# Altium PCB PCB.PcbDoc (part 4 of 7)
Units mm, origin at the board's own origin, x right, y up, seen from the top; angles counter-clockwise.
Board outline 243.2 x 142.8 mm, 4 copper layers (Top Layer, Layer 1, Layer 2, Bottom Layer), stack 0.603 mm thick; 451 components, 380 nets, 2276 pads, 1520 vias.
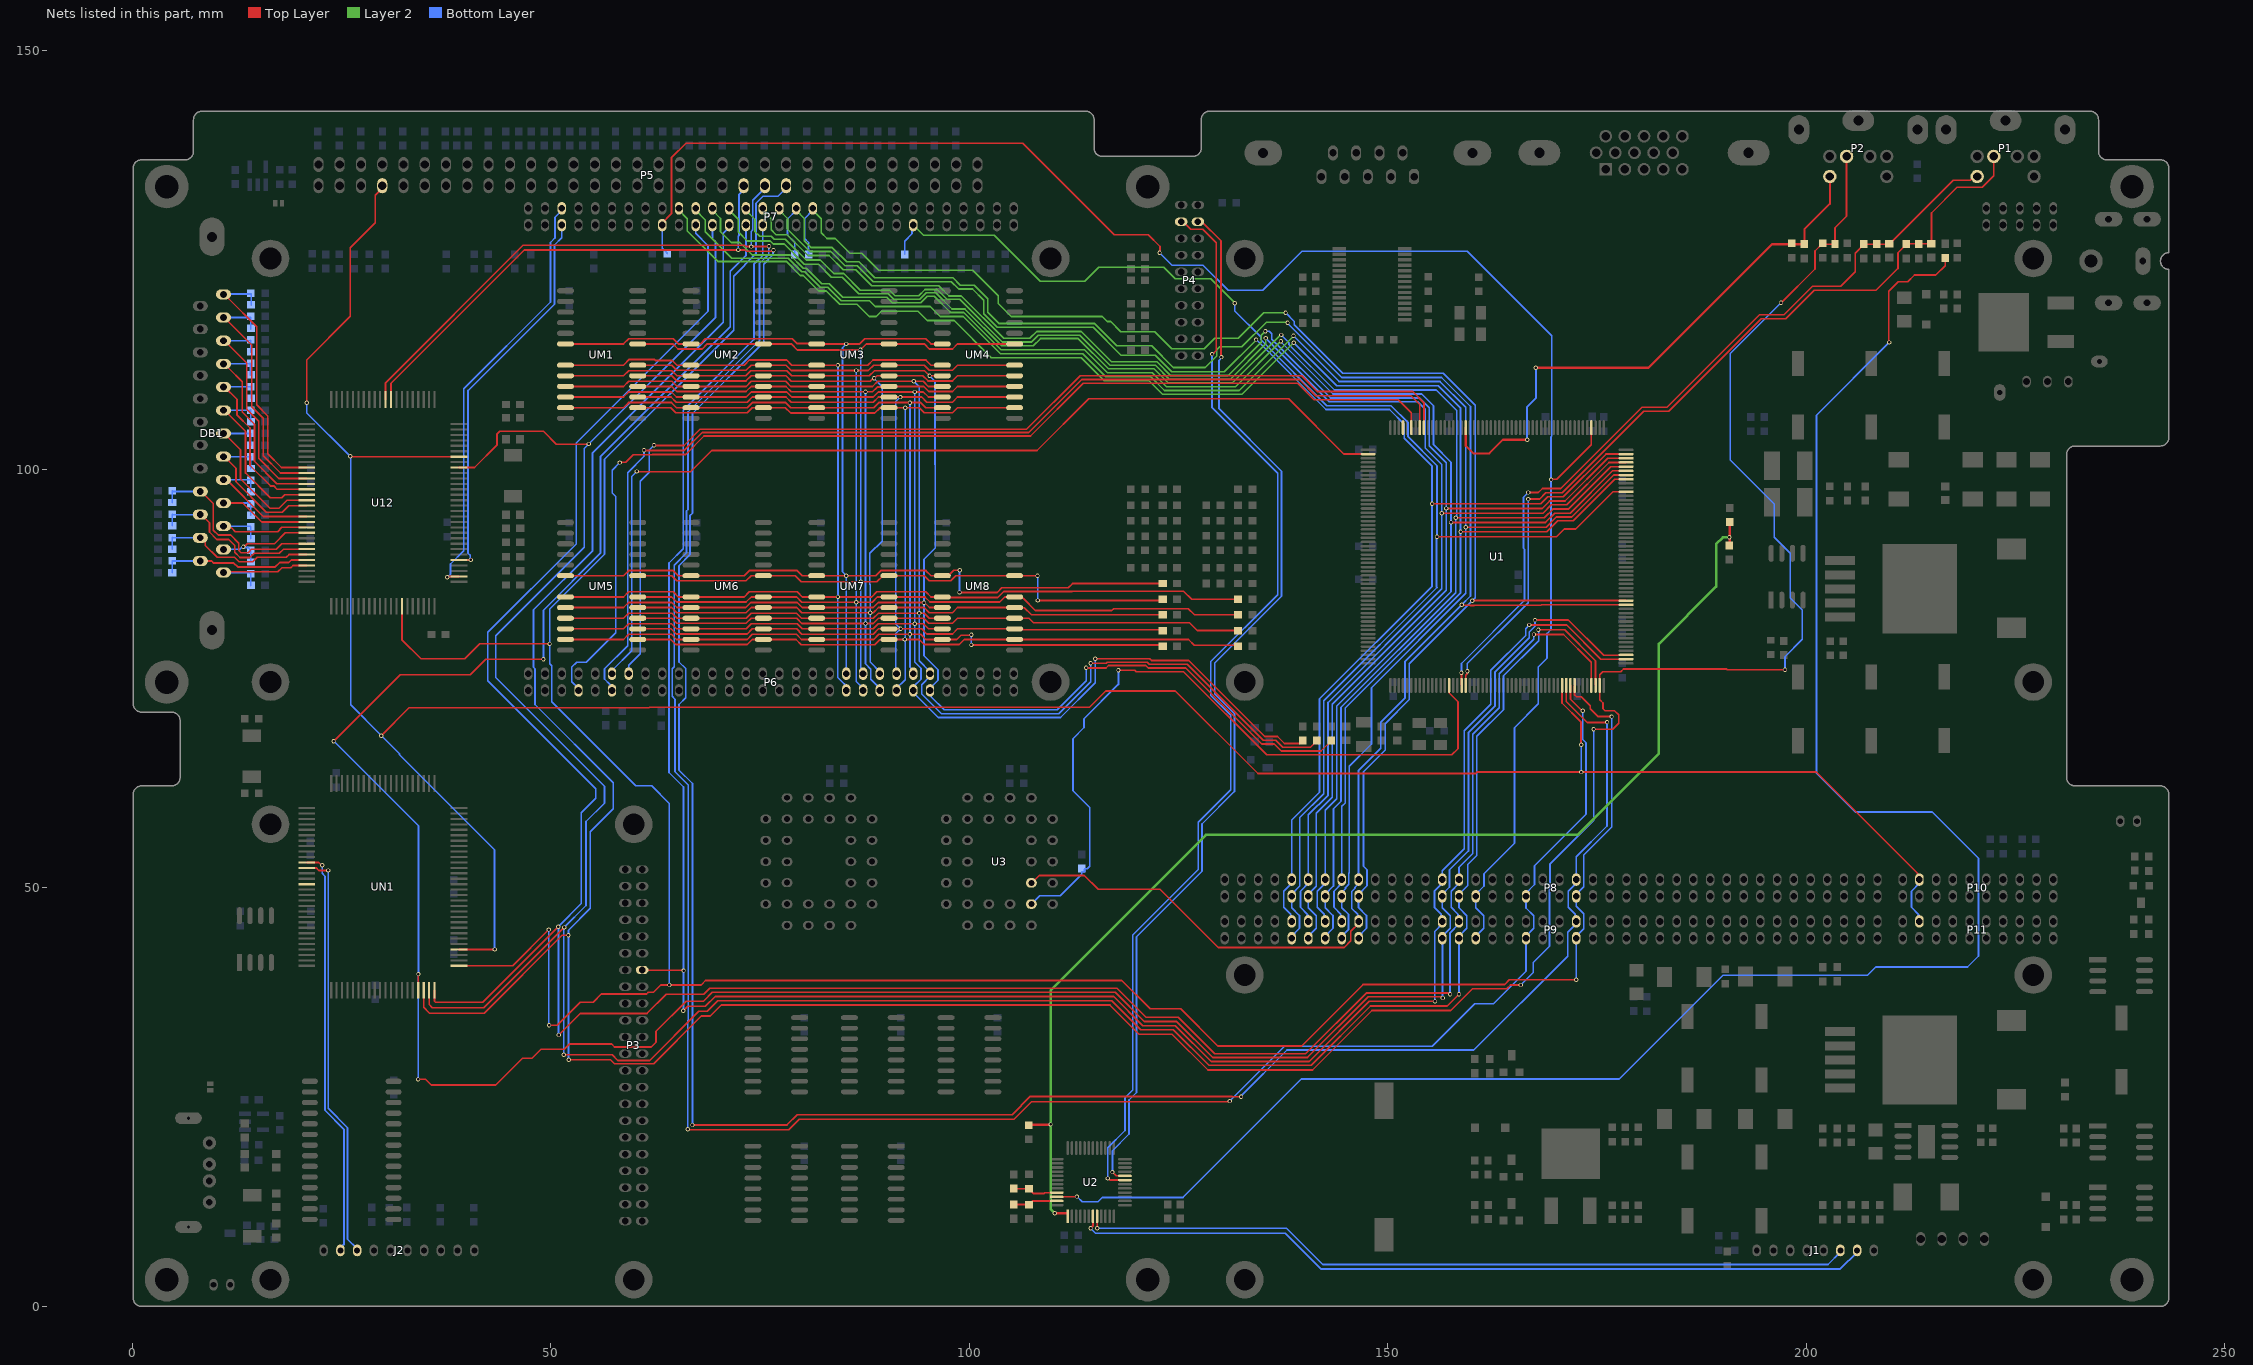
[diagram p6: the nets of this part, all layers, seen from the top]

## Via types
v1: diameter 0.508, hole 0.305, Top Layer to Bottom Layer, tented both sides, 1451 vias
v2: diameter 0.508, hole 0.3, Top Layer to Bottom Layer, 67 vias
v3: diameter 1.2, hole 1.2, Top Layer to Bottom Layer, 2 vias

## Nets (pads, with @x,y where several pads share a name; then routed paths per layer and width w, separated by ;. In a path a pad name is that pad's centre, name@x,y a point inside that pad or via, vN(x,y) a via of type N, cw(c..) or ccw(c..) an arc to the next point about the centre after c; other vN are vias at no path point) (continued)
IRQ5: P5.45 P8.38 P9.38 U1.149 U12.94 UN1.1 | length 334.8
  Top Layer w0.203: U12.94@32.201,83.654 32.201,79.662 34.479,77.384 39.711,77.384 41.489,79.162 v1(49.846,79.162) ; UN1.1@39.026,40.7 45.424,40.7 v1(49.759,45.034) ; v1(49.784,33.604) 50.749,33.604 53.492,36.347 55.042,36.347 56.032,37.338 61.426,37.338 61.629,37.541 62.255,37.541 63.119,38.405 v1(64.16,38.405) 67.945,38.405 68.478,38.938 118.212,38.938 121.59,35.56 125.247,35.56 129.683,31.125 139.689,31.125 147.035,38.471 163.947,38.471 164.506,39.03 v1(172.503,39.03) ; U1.149@172.305,74.206 172.305,73.061 172.528,72.837 173.118,72.837 174.193,71.762 174.193,71.401 175.119,70.475 v1(176.719,70.475)
  Bottom Layer w0.203: v1(49.759,45.034) 49.735,45.01 49.735,33.654 v1(49.784,33.604) ; v1@64.146,38.405 64.146,60.087 62.038,62.195 60.158,62.195 50.114,72.239 50.114,76.532 49.846,76.8 49.846,83.328 56.399,89.881 56.399,101.209 71.842,116.652 71.842,123.104 74.495,125.757 74.495,131.783 75.341,132.629 77.139,132.629 78.11,133.6 P5.45@78.11,133.9 ; v1(172.503,39.03) 172.501,39.031 172.501,43.999 P9.38@172.5,44 172.5,44.25 173.392,45.142 173.392,46.929 172.5,47.821 P8.38@172.5,49 172.5,49.25 173.392,50.142 173.392,53.94 176.744,57.293 v1@176.744,70.475
IRQ6: P5.43 P8.44 P9.44 U1.148 U12.40 | length 320.3
  Top Layer w0.203: U12.40@30.251,108.354 30.251,110.37 46.667,126.787 73.121,126.787 73.273,126.635 v1(73.927,126.635) 73.94,126.647 76.046,126.647 v1(76.059,126.66) ; v1@66.539,21.123 78.425,21.123 79.68,22.377 105.334,22.377 107.417,24.46 130.843,24.46 130.861,24.478 131.056,24.478 v1(131.115,24.536) ; U1.148@171.805,74.206 171.805,72.57 v1@173.239,71.136
  Bottom Layer w0.203: v1(66.345,21.158) 66.356,21.169 66.356,34.162 66.407,34.213 66.407,62.3 64.832,63.875 64.832,72.558 64.495,72.895 64.495,76.183 64.73,76.419 64.73,88.56 66.204,90.033 66.204,95.037 66.381,95.215 66.381,106.872 74.916,115.407 74.916,124.603 76.04,125.727 76.04,126.641 v1(76.059,126.66) ; v1(73.927,126.635) 73.927,128.439 74.114,128.626 74.114,132.144 75.57,133.6 P5.43@75.57,133.9 ; v1@131.102,24.549 137.643,31.09 155.296,31.09 160.376,36.17 162.611,36.17 166.5,40.059 P9.44@166.5,44 166.5,44.25 167.423,45.173 167.423,46.675 166.5,47.598 P8.44@166.5,49 166.5,49.385 167.524,50.409 167.524,52.67 173.671,58.817 173.671,67.354 173.29,67.735 v1(173.29,71.186)
IRQ7: P5.41 P8.37 P9.37 U1.147 U12.39 | length 324
  Top Layer w0.203: U12.39@30.901,108.354 30.901,110.305 46.823,126.228 v1(72.376,126.228) 73.232,126.228 73.385,126.076 v1@76.395,126.076 ; v1(66.915,21.682) 66.925,21.692 78.207,21.692 79.426,22.911 105.105,22.911 107.29,25.095 131.346,25.095 131.397,25.044 v1(132.461,25.044) ; P5.41@73.03,133.6 P5.41@73.03,133.9 ; U1.147@171.305,74.206 171.305,72.28 173.817,69.768 176.139,69.768 v1(176.186,69.815)
  Bottom Layer w0.203: v1(66.915,21.682) 66.915,62.474 65.315,64.074 65.315,71.923 66.105,72.713 66.105,76.213 65.315,77.003 65.315,88.509 66.61,89.805 66.61,94.453 66.915,94.758 66.915,106.687 75.424,115.196 75.424,124.533 76.54,125.65 76.54,126.139 v1(76.599,126.197) ; v1(72.376,126.228) 72.376,127.848 72.486,127.958 72.486,132.865 73.03,133.409 P5.41@73.03,133.9 ; v1@132.41,25.095 137.947,30.632 160.274,30.632 171.487,41.845 171.487,44.698 172.5,45.711 P9.37@172.5,46 172.384,46.116 172.384,46.865 171.558,47.691 171.558,49.622 P8.37@172.5,50.564 ; P8.37@172.5,51 172.5,53.709 176.186,57.394 v1(176.186,69.815)
IRQ9: P5.7 P10.17 P11.17 U1.146 U12.24 UN1.4 | length 334
  Top Layer w0.203: v1(20.834,107.966) 20.834,113.076 26.046,118.288 26.046,126.508 29.018,129.479 29.018,132.768 29.85,133.6 P5.7@29.85,133.9 ; v1@26.021,101.529 U12.24@39.026,101.529 ; v1(29.725,68.193) 33.048,71.517 61.711,71.517 61.774,71.58 114.351,71.58 116.304,73.533 124.612,73.533 134.477,63.669 160.478,63.669 160.655,63.846 v1(173.112,63.846) 201.179,63.846 213.272,51.753 213.272,51.694 213.5,51.466 P10.17@213.5,51 ; UN1.4@39.026,42.65 39.032,42.656 43.301,42.656 v1(43.307,42.662) ; U1.146@170.805,74.206 170.805,72.097 173.061,69.84 173.061,67.173 v1(173.112,67.122)
  Bottom Layer w0.203: v1(20.834,107.966) 20.834,106.751 v1(26.021,101.565) 26.072,101.514 26.072,71.875 29.725,68.222 v1(29.725,68.193) ; v1@29.739,68.208 31.914,66.033 31.914,65.903 43.269,54.548 v1@43.269,42.611 ; v1(173.112,63.846) v1(173.112,67.122) ; P11.17@213.5,46 213.384,46.116 213.384,46.865 212.558,47.691 212.558,49.622 P10.17@213.5,50.564
IRQ10: P7.21 P8.51 P9.51 U1.153 UN1.100 | length 308.8
  Top Layer w0.203: UN1.100@36.101,37.775 36.101,36.469 36.232,36.338 41.852,36.338 v1@50.878,45.363 ; v1(50.927,32.436) 53.496,35.005 61.472,35.005 63.779,37.313 68.275,37.313 68.986,38.024 74.27,38.024 117.627,38.024 121.107,34.544 124.943,34.544 129.311,30.175 140.157,30.175 147.422,37.44 157.22,37.44 157.347,37.313 v1(157.429,37.313) ; v1(167.448,80.28) 170.979,80.28 174.305,76.954 U1.153@174.305,74.206
  Bottom Layer w0.203: v1(50.927,32.436) 50.903,32.46 50.903,45.338 v1(50.876,45.364) 50.876,45.367 53.645,48.136 53.645,58.986 55.358,60.699 55.358,61.839 42.455,74.742 42.455,80.534 53.021,91.1 53.021,103.165 68.775,118.919 68.775,126.73 67.3,128.205 P7.21@67.3,129.2 ; v1(157.429,37.313) 157.429,44.64 158.5,45.711 P9.51@158.5,46 ; P9.51@158.384,46.116 158.384,46.865 157.558,47.691 157.558,49.622 P8.51@158.5,50.564 ; P8.51@158.5,51 158.5,52.485 160.125,54.11 160.125,68.345 163.292,71.512 163.292,75.576 167.416,79.699 167.416,80.247 v1(167.448,80.28)
IRQ11: P7.23 P8.52 P9.52 U1.154 U12.22 UN1.99 | length 334.7
  Top Layer w0.203: UN1.99@35.451,37.775 35.451,36.077 35.84,35.688 41.99,35.688 v1@51.589,45.287 ; U12.22@39.026,100.229 40.865,100.229 43.572,102.936 43.572,104.257 43.877,104.562 49.109,104.562 50.659,103.013 54.494,103.013 v1(54.532,103.051) ; v1(51.537,30.074) 57.328,30.074 58.006,29.395 61.806,29.395 67.666,35.255 68.682,35.255 69.952,36.525 117.018,36.525 120.472,33.071 124.358,33.071 128.626,28.804 140.843,28.804 147.93,35.89 157.099,35.89 v1(158.496,37.287) ; v1(167.981,80.838) 171.127,80.838 174.805,77.161 U1.154@174.805,74.206
  Bottom Layer w0.203: v1(51.537,30.074) 51.537,45.237 54.204,47.904 54.204,57.945 56.399,60.14 56.399,62.163 43.42,75.142 43.42,80.134 53.986,90.7 53.986,102.505 v1(54.532,103.051) 69.677,118.195 69.677,127.225 69.3,127.602 P7.23@69.3,129.2 ; v1(158.496,37.287) 158.498,37.289 158.498,43.998 P9.52@158.5,44 158.5,44.25 159.437,45.187 159.437,46.701 158.5,47.638 P8.52@158.5,49 158.5,49.25 159.549,50.299 159.549,52.797 160.631,53.879 160.631,68.11 163.816,71.295 163.816,75.359 168.007,79.55 v1@168.007,80.838
  other v1: 51.587,45.288
IRQ12: C7.1 P2.1 P7.25 R44.1 U1.155 UN1.98 | length 403.2
  Top Layer w0.203: UN1.98@34.801,37.775 34.801,35.737 35.5,35.038 42.023,35.038 51.333,44.348 v1(52.095,44.348) ; v1(52.121,29.489) 57.125,29.489 57.6,29.014 62.288,29.014 67.97,34.696 69.037,34.696 70.358,36.017 116.789,36.017 120.269,32.537 124.206,32.537 128.499,28.245 140.995,28.245 148.107,35.357 157.5,35.357 160.116,37.973 164.211,37.973 164.643,38.405 v1(165.862,38.405) ; v1(174.578,68.977) 176.871,68.977 177.583,69.688 177.583,70.678 177.075,71.186 175.932,71.186 175.703,71.415 175.703,72.101 175.305,72.499 U1.155@175.305,74.206 175.305,75.462 175.678,75.835 177.811,75.835 178.141,76.165 190.46,76.165 190.562,76.063 v1(197.445,76.063) ; v1(196.963,119.929) 197.014,119.929 201.03,123.946 201.03,126.105 C7.1@201.941,127.016 202.043,126.914 R44.1@203.414,126.914 203.414,128.87 204.8,130.255 P2.1@204.8,137.4
  Bottom Layer w0.203: v1(52.121,29.489) 52.108,29.502 52.108,44.336 v1(52.095,44.348) 52.095,44.958 54.712,47.574 54.712,56.723 57.441,59.452 57.441,62.576 48.105,71.912 48.105,76.183 47.916,76.373 47.916,83.22 54.983,90.287 54.983,102.003 70.579,117.598 70.579,128.229 71.3,128.95 P7.25@71.3,129.2 ; v1(165.862,38.405) 167.361,39.903 167.361,41.097 169.305,43.041 169.305,49.908 169.378,49.981 169.378,52.898 174.578,58.098 v1(174.578,68.977) ; v1(196.963,119.929) 190.892,113.858 190.892,101.133 196.15,95.875 196.15,91.913 198.055,90.008 198.055,84.648 199.503,83.201 199.503,79.695 197.445,77.638 v1(197.445,76.063)
IRQ14: P3.31 P7.29 P8.53 P9.53 U1.158 | length 264.2
  Top Layer w0.203: P3.31@60.9,40.2 60.934,40.166 65.814,40.166 v1(65.848,40.132) ; v1(65.811,35.331) 66.345,35.865 68.453,35.865 69.621,37.033 117.246,37.033 120.726,33.553 124.587,33.553 128.88,29.261 140.589,29.261 147.777,36.449 v1(155.626,36.449) ; v1(166.889,81.423) 171.36,81.423 175.446,77.336 U1.158@178.463,77.336
  Bottom Layer w0.203: v1@65.842,35.331 65.842,40.126 v1(65.848,40.132) 65.848,62.068 64.114,63.802 64.114,88.833 65.823,90.541 65.823,107.094 74.255,115.527 74.255,124.526 75.3,125.571 P7.29@75.3,129.2 ; v1(155.626,36.449) 155.586,36.489 155.586,44.797 156.5,45.711 P9.53@156.5,46 156.384,46.116 156.384,46.865 155.558,47.691 155.558,49.622 P8.53@156.5,50.564 ; P8.53@156.5,51 156.5,52.06 159.114,54.674 159.114,68.764 162.281,71.931 162.281,75.995 166.452,80.166 166.452,80.986 v1(166.889,81.423)
IRQ15: P7.27 P8.54 P9.54 U1.159 UN1.97 | length 335.5
  Top Layer w0.203: v1(24.04,67.529) 31.99,75.479 40.346,75.479 42.205,77.337 v1(49.109,77.337) ; v1(34.138,27.127) 34.163,27.153 35.027,27.153 35.712,26.467 43.409,26.467 46.609,29.667 47.752,29.667 48.819,30.734 51.613,30.734 52.248,31.369 57.243,31.369 57.607,31.005 62.001,31.005 62.56,31.564 62.56,32.87 66.164,36.474 68.224,36.474 69.291,37.541 117.424,37.541 120.929,34.036 124.765,34.036 129.057,29.743 140.386,29.743 147.65,37.008 156.331,37.008 156.483,36.855 v1(156.566,36.855) ; UN1.97@34.151,37.775 34.162,37.787 34.162,39.704 v1(34.174,39.716) ; P7.27@73.3,129.2 P7.27@73.3,129.45 ; v1(167.575,82.007) 171.563,82.007 175.779,77.79 177.449,77.79 177.476,77.817 178.444,77.817 U1.159@178.463,77.836
  Bottom Layer w0.203: v1@24.065,67.554 34.174,57.445 v1(34.174,39.716) 34.156,39.698 34.156,27.146 v1(34.138,27.127) ; v1(49.109,77.337) 49.109,83.175 55.917,89.982 55.917,101.539 71.436,117.059 71.436,123.688 73.3,125.552 P7.27@73.3,129.2 ; P9.54@156.5,44 156.533,43.967 156.533,36.888 v1(156.566,36.855) ; P9.54@156.5,44.25 157.437,45.187 157.437,46.701 156.5,47.638 P8.54@156.5,49 156.5,49.25 157.364,50.114 157.364,52.162 159.62,54.417 159.62,68.554 162.787,71.721 162.787,75.785 166.889,79.888 166.889,80.584 167.575,81.27 v1(167.575,82.007)
JP: UN1.65
KB_RxD: J1.3 U2.20 | length 92.8
  Top Layer w0.203: U2.20@115.256,10.778 115.273,10.76 115.273,9.364 v1(115.291,9.347)
  Bottom Layer w0.203: v1(115.291,9.347) 115.3,9.337 137.89,9.337 142.208,5.019 202.586,5.019 204.063,6.496 J1.3@204.063,6.696
KB_TxD: J1.2 U2.19 | length 96.2
  Top Layer w0.254: v1(114.478,9.347) 114.756,9.625 U2.19@114.756,10.778
  Bottom Layer w0.203: v1(114.478,9.347) 115.074,8.751 137.722,8.751 141.987,4.486 204.053,4.486 206.063,6.496 J1.2@206.063,6.696
KBCLK: C6.1 P1.5 R19.1 R41.1 U1.122 | length 97
  Top Layer w0.203: v1(158.787,75.708) 158.796,75.699 158.796,74.215 U1.122@158.805,74.206 ; v1(166.762,97.247) 167.981,97.247 168.464,97.729 170.648,97.729 180.351,107.432 183.348,107.432 194.397,118.481 197.322,118.481 200.725,121.885 204.1,121.885 205.827,123.612 205.827,125.835 206.869,126.876 R41.1@206.869,126.914 R19.1@208.393,126.914 209.866,126.914 C6.1@209.917,126.965 209.955,126.965 217.549,134.559 219.583,134.559 219.971,134.948 P1.5@220.348,134.948
  Bottom Layer w0.203: v1(158.787,75.708) 158.787,76.825 166.318,84.356 166.318,90.466 166.203,90.581 166.203,96.691 166.759,97.247 v1(166.762,97.247)
KBDATA: C5.1 P1.1 R20.1 R42.1 U1.123 | length 102.5
  Top Layer w0.203: U1.123@159.305,74.206 159.305,75.411 159.439,75.545 159.439,75.827 v1(159.498,75.885) ; v1(166.762,96.459) 168.108,96.459 168.87,97.221 170.826,97.221 180.554,106.95 183.548,106.95 194.597,117.999 197.522,117.999 200.925,121.402 208.317,121.402 210.933,124.018 210.933,125.86 211.949,126.876 R42.1@211.949,126.914 212,126.965 C5.1@214.946,126.965 214.946,130.648 217.998,133.7 220.995,133.7 222.4,135.105 P1.1@222.4,137.4
  Bottom Layer w0.203: v1(159.498,75.885) 159.498,76.825 166.762,84.09 v1(166.762,96.459)
KBSJ: R23.2 U1.119 U3.22 | length 88.8
  Top Layer w0.203: v1(117.805,76.022) 119.756,76.022 119.934,75.844 125.578,75.844 135.516,65.906 157.646,65.906 158.38,66.64 158.38,72.237 157.323,73.294 157.323,74.187 U1.119@157.305,74.206
  Bottom Layer w0.203: U3.22@107.402,48.072 108.393,49.063 110.857,49.063 113.44,51.646 113.44,51.933 113.727,51.933 113.759,51.965 113.759,52.252 113.79,52.284 114.078,52.284 114.376,52.582 114.376,59.614 112.37,61.62 112.37,67.843 113.69,69.164 113.69,70.206 117.805,74.32 v1(117.805,76.022)
LA17: P7.32 P8.71 P9.71 U1.207 | length 184
  Top Layer w0.203: v1(155.281,95.901) 168.27,95.901 169.108,96.739 170.953,96.739 176.05,101.836 U1.207@178.463,101.836
  Layer 2 w0.203: P7.32@77.3,131.2 77.3,130.95 78.269,129.981 78.269,128.692 80.92,126.041 83.435,126.041 85.136,124.339 86.61,124.339 88.515,122.434 97.851,122.434 98.729,121.556 100.38,121.556 101.714,120.222 101.714,118.586 103.316,116.984 114.793,116.984 118.121,113.655 122.211,113.655 124.192,111.674 130.466,111.674 134.252,115.46 v1(134.252,115.522)
  Bottom Layer w0.203: v1(134.252,115.522) 142.607,107.167 150.187,107.167 151.962,105.392 151.962,103.716 155.281,100.396 v1(155.281,95.901) 155.281,86.045 141.828,72.592 141.828,61.441 138.5,58.113 P8.71@138.5,51 ; P9.71@138.384,46.116 138.384,46.865 137.558,47.691 137.558,49.622 P8.71@138.5,50.564
LA18: P7.30 P8.70 P9.70 U1.206 | length 192.2
  Top Layer w0.203: v1(156.983,95.342) 168.423,95.342 169.317,96.236 171.162,96.236 176.261,101.336 U1.206@178.463,101.336
  Layer 2 w0.203: P7.30@75.3,131.2 75.3,130.95 76.313,129.937 76.313,128.641 76.897,128.057 78.218,128.057 80.719,125.556 83.234,125.556 84.936,123.854 86.437,123.854 88.342,121.949 96.34,121.949 97.573,120.716 99.04,120.716 104.095,115.662 107.225,115.662 108.051,116.488 113.369,116.488 116.975,112.881 122.411,112.881 124.075,111.217 130.897,111.217 134.86,115.179 134.86,116.017 v1(135.368,116.525)
  Bottom Layer w0.203: v1(135.368,116.525) 135.825,116.525 136.13,116.221 136.13,115.557 143.137,108.55 153.783,108.55 154.951,107.381 154.951,102.835 156.983,100.803 v1(156.983,95.342) 156.983,85.568 143.369,71.954 143.369,60.849 141.438,58.918 141.438,50.188 140.5,49.25 140.5,47.638 141.437,46.701 141.437,45.187 140.5,44.25 P9.70@140.5,44
LA19: P7.28 P8.69 P9.69 U1.205 | length 191.4
  Top Layer w0.203: v1(156.424,94.783) 168.524,94.783 169.51,95.769 171.355,95.769 176.422,100.836 U1.205@178.463,100.836
  Layer 2 w0.203: P7.28@73.3,131.2 73.3,130.95 74.382,129.868 74.382,128.413 74.941,127.854 76.313,127.854 76.668,127.498 78.015,127.498 80.496,125.017 82.188,125.017 83.796,123.409 84.974,123.409 86.981,121.402 90.461,121.402 91.121,120.742 93.943,120.742 94.705,121.504 96.156,121.504 97.324,120.335 98.835,120.335 103.954,115.217 107.409,115.217 108.235,116.043 113.184,116.043 116.791,112.436 122.227,112.436 123.89,110.772 131.189,110.772 135.419,115.001 v1(135.419,115.701)
  Bottom Layer w0.203: v1(135.419,115.701) 135.419,115.681 143.007,108.093 153.58,108.093 154.469,107.204 154.469,102.555 156.424,100.6 v1(156.424,94.783) 156.424,85.736 142.855,72.166 142.855,61.097 140.5,58.742 P8.69@140.5,51 ; P9.69@140.5,46 140.384,46.116 140.384,46.865 139.558,47.691 139.558,49.622 P8.69@140.5,50.564
LA20: P7.26 P8.68 P9.68 U1.204 | length 197.2
  Top Layer w0.203: v1(158.101,94.224) 168.677,94.224 169.718,95.266 171.563,95.266 176.633,100.336 U1.204@178.463,100.336
  Layer 2 w0.203: P7.26@71.3,131.2 71.3,130.95 72.376,129.874 72.376,128.387 73.468,127.295 76.214,127.295 76.57,126.939 77.862,126.939 80.288,124.514 81.979,124.514 83.516,122.977 84.796,122.977 86.778,120.996 90.292,120.996 90.953,120.335 94.076,120.335 94.838,121.097 95.987,121.097 97.918,119.167 99.464,119.167 103.859,114.773 107.631,114.773 108.495,115.636 113.016,115.636 116.623,112.03 122.058,112.03 123.76,110.328 131.405,110.328 137.005,115.927 137.024,115.927 137.165,116.068 v1(137.247,116.068)
  Bottom Layer w0.203: v1@137.249,116.07 138.187,115.131 138.187,114.919 143.617,109.49 155.789,109.49 158.228,107.051 158.228,94.434 158.101,94.307 v1(158.101,94.224) 158.101,85.283 144.396,71.579 144.396,60.378 143.496,59.477 143.496,50.246 142.5,49.25 P8.68@142.5,49 142.5,47.638 143.437,46.701 143.437,45.187 P9.68@142.5,44.25
LA21: P7.24 P8.67 P9.67 U1.203 | length 194.5
  Top Layer w0.203: v1(157.542,93.678) 157.555,93.665 168.82,93.665 169.924,94.77 171.769,94.77 176.835,99.836 U1.203@178.463,99.836
  Layer 2 w0.203: P7.24@69.3,131.2 69.3,130.95 70.268,129.982 70.268,128.387 71.538,127.117 72.579,127.117 74.078,125.619 78.573,125.619 80.148,124.044 80.504,124.044 82.358,122.19 83.272,122.19 84.873,120.589 90.124,120.589 90.784,119.929 94.208,119.929 94.97,120.691 95.819,120.691 97.749,118.761 99.332,118.761 103.777,114.316 113.752,114.316 116.496,111.572 121.855,111.572 123.544,109.883 131.796,109.883 137.219,115.306 v1(137.222,115.306)
  Bottom Layer w0.203: v1(137.222,115.306) 137.222,115.227 143.442,109.007 154.037,109.007 155.459,107.585 155.459,102.962 157.542,100.879 v1(157.542,93.678) 157.542,85.4 143.883,71.741 143.883,60.651 142.5,59.269 P8.67@142.5,51 ; P9.67@142.384,46.116 142.384,46.865 141.558,47.691 141.558,49.622 P8.67@142.5,50.564
LA22: P7.22 P8.66 P9.66 U1.202 | length 200
  Top Layer w0.203: v1(159.306,93.107) 168.905,93.107 170.113,94.314 171.958,94.314 176.979,99.336 U1.202@178.463,99.336
  Layer 2 w0.203: P7.22@67.3,131.2 67.3,130.95 68.439,129.811 68.439,128.413 71.614,125.238 78.344,125.238 79.969,123.612 80.325,123.612 82.179,121.758 83.094,121.758 84.694,120.158 88.07,120.158 88.756,119.472 95.314,119.472 96.508,118.278 99.276,118.278 103.721,113.833 113.553,113.833 116.296,111.09 121.655,111.09 123.307,109.438 132.243,109.438 138.721,115.916 v1(138.721,115.967)
  Bottom Layer w0.203: v1(138.721,115.967) 144.17,110.517 156.215,110.517 159.306,107.426 v1(159.306,93.107) 159.306,85.193 148.042,73.93 148.042,67.199 145.375,64.532 145.375,51.802 145.314,51.741 145.314,50.426 144.933,50.045 144.933,49.899 144.5,49.466 P8.66@144.5,49 144.5,47.638 145.305,46.833 145.305,45.055 P9.66@144.5,44.25
LA23: P7.20 P8.65 P9.65 U1.201 | length 199.6
  Top Layer w0.203: v1(158.685,92.548) 168.981,92.548 170.299,93.865 172.144,93.865 177.114,98.836 U1.201@178.463,98.836
  Layer 2 w0.203: P7.20@65.3,131.2 65.3,130.95 66.305,129.945 66.305,128.489 69.937,124.857 78.114,124.857 79.79,123.18 80.146,123.18 82,121.326 82.915,121.326 84.515,119.726 86.574,119.726 88.022,118.278 88.886,118.278 89.495,118.888 93.867,118.888 94.959,117.795 98.178,117.795 102.623,113.35 113.353,113.35 116.096,110.607 121.455,110.607 123.069,108.994 132.561,108.994 138.718,115.151 v1(138.746,115.151)
  Bottom Layer w0.203: v1(138.746,115.151) 138.746,115.126 143.879,109.992 155.998,109.992 158.685,107.305 v1(158.685,92.548) 158.685,85.278 144.91,71.503 144.91,60.155 144.5,59.745 P8.65@144.5,51 ; P9.65@144.384,46.116 144.384,46.865 143.558,47.691 143.558,49.622 P8.65@144.5,50.564
LEDACT: J2.8 UN1.62 | length 49.5
  Top Layer w0.203: UN1.62@20.826,52.4 20.83,52.395 21.976,52.395 22.286,52.086 23.384,52.086 v1(23.393,52.095)
  Bottom Layer w0.203: v1(23.393,52.095) 23.393,23.672 25.705,21.361 25.705,8.045 26.854,6.896 J2.8@26.854,6.696
LEDLINK: J2.9 UN1.61 | length 49.3
  Top Layer w0.203: UN1.61@20.826,53.05 22.255,53.05 22.6,52.705 v1(22.682,52.705)
  Bottom Layer w0.203: v1(22.682,52.705) 22.682,51.74 23.012,51.41 23.012,23.446 25.273,21.185 25.273,7.413 24.854,6.995 J2.9@24.854,6.696
LPT_ACK#: C105.1 DB1.10 R125.1 U12.62 | length 25.1
  Top Layer w0.203: DB1.10@10.985,112.61 11.015,112.61 11.476,112.15 11.476,112.119 13.118,110.477 13.118,106.873 14.581,105.41 14.581,100.965 17.267,98.279 U12.62@20.826,98.279
  Bottom Layer w0.203: DB1.10@10.908,112.639 14.05,112.639 14.082,112.671 R125.1@14.082,111.274
LPT_ATUOFD#: C101.1 DB1.14 R121.1 U12.76 | length 18.1
  Top Layer w0.203: DB1.14@8.215,89.065 9.488,89.065 9.739,88.814 12.127,88.814 12.584,88.357 17.08,88.357 17.613,88.89 18.68,88.89 18.969,89.179 U12.76@20.826,89.179
  Bottom Layer w0.203: R121.1@4.761,87.671 C101.1@4.761,89.068 4.764,89.065 DB1.14@8.215,89.065
LPT_BUSY: C106.1 DB1.11 R126.1 U12.61 | length 27.1
  Top Layer w0.203: DB1.11@10.985,115.38 11.015,115.38 11.476,114.92 11.476,114.889 13.651,112.714 13.651,107.204 15.109,105.746 15.109,101.326 17.506,98.929 U12.61@20.826,98.929
  Bottom Layer w0.203: DB1.11@10.985,115.38 14.127,115.38 14.159,115.412 R126.1@14.159,114.015
LPT_D0: C109.1 DB1.2 R129.1 U12.71 | length 13.4
  Top Layer w0.203: DB1.2@10.985,90.45 DB1.2@11.285,90.45 ; v1(13.27,90.77) 13.349,90.77 13.705,91.125 16.978,91.125 18.282,92.429 U12.71@20.826,92.429
  Bottom Layer w0.203: DB1.2@10.985,90.45 12.842,90.45 13.162,90.77 13.327,90.77 13.41,90.686 13.811,90.686 C109.1@14.159,90.338 R129.1@14.159,88.941
LPT_D1: C110.1 DB1.3 R130.1 U12.70 | length 14.9
  Top Layer w0.203: DB1.3@10.985,93.22 11.176,93.029 11.849,93.029 12.305,92.573 17.359,92.573 17.865,93.079 U12.70@20.826,93.079
  Bottom Layer w0.203: DB1.3@10.985,93.22 14.071,93.22 C110.1@14.159,93.132 R130.1@14.159,91.735
LPT_D2: C111.1 DB1.4 R131.1 U12.69 | length 15.4
  Top Layer w0.203: DB1.4@10.985,95.99 13.181,95.99 15.442,93.729 U12.69@20.826,93.729
  Bottom Layer w0.203: DB1.4@10.985,95.99 14.095,95.99 C111.1@14.159,95.926 R131.1@14.159,94.529
LPT_D3: C112.1 DB1.5 R132.1 U12.68 | length 16.2
  Top Layer w0.203: DB1.5@10.985,98.76 11.274,98.76 15.655,94.379 U12.68@20.826,94.379
  Bottom Layer w0.203: DB1.5@10.985,98.76 14.119,98.76 C112.1@14.159,98.72 R132.1@14.159,97.323
LPT_D4: C113.1 DB1.6 R133.1 U12.66 | length 18.5
  Top Layer w0.203: DB1.6@10.985,101.53 11.015,101.53 11.476,101.07 11.476,101.039 12.381,100.134 12.381,98.517 16.013,94.885 17.893,94.885 18.687,95.679 U12.66@20.826,95.679
  Bottom Layer w0.203: DB1.6@10.985,101.53 14.143,101.53 C113.1@14.159,101.514 R133.1@14.159,100.117
LPT_D5: C114.1 DB1.7 R134.1 U12.65 | length 20.6
  Top Layer w0.203: DB1.7@10.985,104.3 11.015,104.3 11.476,103.84 11.476,103.809 12.914,102.371 12.914,98.898 16.445,95.367 17.512,95.367 18.473,96.329 U12.65@20.826,96.329
  Bottom Layer w0.203: DB1.7@10.985,104.3 14.151,104.3 C114.1@14.159,104.308 R134.1@14.159,102.911
LPT_D6: C115.1 DB1.8 R135.1 U12.64 | length 21.8
  Top Layer w0.203: DB1.8@10.985,107.07 11.015,107.07 11.476,106.61 11.476,106.579 13.524,104.531 13.524,99.584 16.47,96.637 17.842,96.637 18.184,96.979 U12.64@20.826,96.979
  Bottom Layer w0.203: DB1.8@10.985,107.07 14.127,107.07 C115.1@14.159,107.102 R135.1@14.159,105.705
LPT_D7: C116.1 DB1.9 R136.1 U12.63 | length 23.2
  Top Layer w0.203: DB1.9@10.985,109.84 11.024,109.84 12.508,108.356 12.508,106.492 14.052,104.948 14.052,100.478 16.496,98.034 16.877,98.034 17.282,97.629 U12.63@20.826,97.629
  Bottom Layer w0.203: DB1.9@11.009,109.896 14.151,109.896 14.183,109.928 R136.1@14.183,108.531
LPT_ERROR#: C102.1 DB1.15 R122.1 U12.75 | length 19.3
  Top Layer w0.203: DB1.15@8.215,91.835 8.244,91.835 8.704,91.375 8.704,90.916 10.12,89.5 12.203,89.5 12.737,88.966 14.388,88.966 14.921,89.5 18.375,89.5 18.704,89.829 U12.75@20.826,89.829
  Bottom Layer w0.203: R122.1@4.761,90.465 C102.1@4.761,91.862 4.788,91.835 DB1.15@8.215,91.835
LPT_INIT#: C103.1 DB1.16 R123.1 U12.74 | length 21.1
  Top Layer w0.203: DB1.16@8.215,94.605 9.206,93.614 9.206,92.521 10.094,91.633 11.517,91.633 12.229,90.922 12.229,90.109 12.864,89.474 14.032,89.474 14.54,89.982 17.563,89.982 18.059,90.479 U12.74@20.826,90.479
  Bottom Layer w0.203: R123.1@4.761,93.259 C103.1@4.761,94.656 4.812,94.605 DB1.16@8.215,94.605
LPT_PE: C107.1 DB1.12 R127.1 U12.60 | length 29.1
  Top Layer w0.203: DB1.12@10.985,118.15 11.015,118.15 11.476,117.69 11.476,117.659 14.261,114.874 14.261,107.483 15.637,106.106 15.637,101.636 17.694,99.579 U12.60@20.826,99.579
  Bottom Layer w0.203: DB1.12@10.985,118.15 14.127,118.15 14.159,118.182 R127.1@14.159,116.881 R127.1@14.159,116.785
LPT_SLCT: C108.1 DB1.13 R128.1 U12.59 | length 31.1
  Top Layer w0.203: DB1.13@10.985,120.92 11.015,120.92 11.476,120.46 11.476,120.429 14.845,117.06 14.845,107.712 16.166,106.391 16.166,101.87 17.806,100.229 U12.59@20.826,100.229
  Bottom Layer w0.203: DB1.13@11.009,120.97 14.151,120.97 14.183,121.002 R128.1@14.183,119.605
LPT_SLCTIN#: C104.1 DB1.17 R124.1 U12.73 | length 23.4
  Top Layer w0.203: DB1.17@8.215,97.375 8.245,97.375 8.706,96.915 8.706,96.884 9.663,95.927 9.663,92.75 10.246,92.167 11.746,92.167 12.711,91.202 12.711,90.33 12.983,90.059 13.829,90.059 14.235,90.465 17.182,90.465 17.845,91.129 U12.73@20.826,91.129
  Bottom Layer w0.203: R124.1@4.761,96.053 C104.1@4.761,97.45 4.836,97.375 DB1.17@8.215,97.375
LPT_STROBE#: C100.1 DB1.1 R120.1 U12.77 | length 14.8
  Top Layer w0.203: DB1.1@10.985,87.68 11.078,87.773 17.385,87.773 17.867,88.255 18.909,88.255 19.182,88.529 U12.77@20.826,88.529
  Bottom Layer w0.203: DB1.1@10.985,87.68 14.023,87.68 C100.1@14.159,87.544 R120.1@14.159,86.147
MA0: P6.49 RM1.2 UM1.8 UM2.8 UM3.8 UM4.8 UM5.8 UM6.8 UM7.8 UM8.8 | length 189.7
  Top Layer w0.203: UM5.8@51.739,83.499 58.673,83.499 59.282,84.109 64.453,84.109 65.062,83.499 UM6.8@66.747,83.499 73.288,83.499 73.898,84.109 79.439,84.109 80.048,83.499 UM7.8@81.756,83.499 88.503,83.499 89.113,84.109 v1@94.575,84.109 ; UM1.8@51.739,111.19 58.673,111.19 59.282,111.799 64.453,111.799 65.062,111.19 UM2.8@66.747,111.19 73.288,111.19 73.898,111.799 78.167,111.799 78.777,111.19 UM3.8@81.756,111.19 88.046,111.19 88.655,111.799 94.628,111.799 v1(95.238,111.19) UM4.8@96.764,111.19 ; v1@94.628,84.109 95.238,83.499 UM8.8@96.764,83.499 ; v1@113.944,76.276 116.323,76.276 116.628,76.581 121.076,76.581 121.381,76.276 125.851,76.276 134.932,67.195 136.431,67.195 137.269,66.357 142.003,66.357 143.213,67.567 RM1.2@143.213,67.605
  Bottom Layer w0.203: v1(95.238,111.19) 95.896,110.531 95.896,100.587 95.922,100.562 95.922,90.617 94.575,89.271 v1(94.575,84.09) 94.575,77.761 96.252,76.084 96.252,74.802 95.3,73.85 P6.49@95.3,73.6 95.452,73.448 95.452,72.824 96.979,71.298 110.49,71.298 113.944,74.752 v1(113.944,76.302)
MA1: P6.50 RM2.2 UM1.9 UM2.9 UM3.9 UM4.9 UM5.9 UM6.9 UM7.9 UM8.9 | length 188.3
  Top Layer w0.203: UM5.9@51.739,82.229 58.673,82.229 59.282,82.839 64.478,82.839 65.088,82.229 UM6.9@66.747,82.229 73.339,82.229 73.949,82.839 79.337,82.839 79.947,82.229 UM7.9@81.756,82.229 88.528,82.229 89.138,82.839 v1(94.017,82.839) 94.603,82.839 95.212,82.229 UM8.9@96.764,82.229 ; UM1.9@51.739,109.92 58.673,109.92 59.282,110.529 64.478,110.529 65.088,109.92 UM2.9@66.747,109.92 73.339,109.92 73.949,110.529 78.066,110.529 78.675,109.92 UM3.9@81.756,109.92 88.43,109.92 89.039,110.529 93.356,110.529 93.358,110.531 94.49,110.531 95.101,109.92 UM4.9@96.764,109.92 ; v1(114.478,76.835) 116.343,76.835 116.47,76.962 121.234,76.962 121.469,76.727 126.038,76.727 135.119,67.646 136.617,67.646 137.456,66.808 140.754,66.808 141.513,67.567 RM2.2@141.513,67.605
  Bottom Layer w0.203: v1(93.356,110.531) 94.017,109.871 v1(94.017,82.839) 94.017,77.133 95.3,75.85 P6.50@95.3,75.6 95.3,75.275 94.296,74.271 94.296,73.179 96.66,70.815 110.69,70.815 114.503,74.629 114.503,76.81 v1(114.478,76.835)
MA2: P6.47 RM3.2 UM1.10 UM2.10 UM3.10 UM4.10 UM5.10 UM6.10 UM7.10 UM8.10 | length 186.4
  Top Layer w0.203: UM5.10@51.739,80.959 58.673,80.959 59.282,81.569 64.402,81.569 65.012,80.959 UM6.10@66.747,80.959 73.339,80.959 73.949,81.569 79.439,81.569 80.048,80.959 UM7.10@81.756,80.959 88.503,80.959 89.113,81.569 v1(93.458,81.569) 94.501,81.569 95.111,80.959 UM8.10@96.764,80.959 ; UM1.10@51.739,108.65 58.673,108.65 59.282,109.259 64.402,109.259 65.012,108.65 UM2.10@66.747,108.65 73.339,108.65 73.949,109.259 78.167,109.259 78.777,108.65 UM3.10@81.756,108.65 88.503,108.65 89.113,109.259 v1(93.458,109.259) 94.501,109.259 95.111,108.65 UM4.10@96.764,108.65 ; v1(115.037,77.394) 121.552,77.394 121.768,77.179 126.225,77.179 135.306,68.097 136.804,68.097 137.643,67.259 139.47,67.259 139.813,67.602 RM3.2@139.813,67.605
  Bottom Layer w0.203: v1(93.458,109.259) v1(93.458,81.569) 93.458,77.003 94.22,76.241 94.22,74.946 93.3,74.026 P6.47@93.3,73.6 93.3,73.35 96.292,70.358 110.879,70.358 115.037,74.515 v1(115.037,77.394)
MA3: P6.48 RM4.2 UM1.11 UM2.11 UM3.11 UM4.11 UM5.11 UM6.11 UM7.11 UM8.11 | length 153.5
  Top Layer w0.203: UM5.11@51.739,79.689 58.673,79.689 59.282,80.299 64.402,80.299 65.012,79.689 UM6.11@66.747,79.689 73.441,79.689 74.05,80.299 79.337,80.299 79.947,79.689 UM7.11@81.756,79.689 88.554,79.689 89.163,80.299 94.196,80.299 94.806,79.689 UM8.11@96.764,79.689 98.481,79.689 98.995,80.203 100.195,80.203 v1(100.24,80.248) ; UM1.11@51.739,107.38 58.673,107.38 59.282,107.989 64.402,107.989 65.012,107.38 UM2.11@66.747,107.38 73.441,107.38 74.05,107.989 78.066,107.989 78.675,107.38 UM3.11@81.756,107.38 88.554,107.38 89.163,107.989 94.196,107.989 94.806,107.38 UM4.11@96.764,107.38 ; v1@100.24,79.029 113.501,79.029 122.946,79.029 RM4.2@123.1,78.875
  Bottom Layer w0.203: v1(92.899,107.966) v1(92.899,80.305) 92.899,76.367 93.3,75.966 P6.48@93.3,75.6 ; v1(100.24,79.035) v1(100.24,80.248)
MA4: P6.45 RM5.2 UM1.14 UM2.14 UM3.14 UM4.14 UM5.14 UM6.14 UM7.14 UM8.14 | length 154.4
  Top Layer w0.203: UM5.14@60.375,79.689 64.326,79.689 64.935,79.08 73.453,79.08 74.063,79.689 79.286,79.689 79.92,79.056 88.683,79.056 89.27,79.644 90.346,79.644 UM7.14@90.392,79.689 93.993,79.689 94.603,79.08 98.786,79.08 99.395,79.689 UM8.14@105.4,79.689 126.179,79.689 126.874,78.994 131.981,78.994 RM5.2@132.1,78.875 ; UM1.14@60.375,107.38 64.326,107.38 64.935,106.77 73.453,106.77 74.063,107.38 UM2.14@75.383,107.38 78.015,107.38 78.648,106.746 88.683,106.746 89.27,107.334 90.346,107.334 UM3.14@90.392,107.38 v1(92.34,107.38) 93.993,107.38 94.603,106.77 97.977,106.77 98.587,107.38 UM4.14@105.4,107.38
  Bottom Layer w0.203: P6.45@91.3,73.6 91.3,73.85 92.334,74.884 92.334,79.651 v1(92.289,79.695) 92.34,79.746 v1(92.34,107.38)
MA5: P6.46 RM6.2 UM1.15 UM2.15 UM3.15 UM4.15 UM5.15 UM6.15 UM7.15 UM8.15 | length 144.7
  Top Layer w0.203: UM5.15@60.375,80.959 64.351,80.959 64.961,80.35 73.45,80.35 74.06,80.959 79.353,80.959 79.986,80.326 88.505,80.326 89.138,80.959 UM7.15@90.392,80.959 94.298,80.959 94.907,80.35 97.977,80.35 98.587,80.959 UM8.15@105.4,80.959 105.478,80.882 106.416,80.882 106.433,80.864 122.986,80.864 RM6.2@123.1,80.75 ; UM1.15@60.375,108.65 64.351,108.65 64.961,108.04 73.45,108.04 74.06,108.65 UM2.15@75.383,108.65 78.082,108.65 78.715,108.016 88.505,108.016 89.138,108.65 UM3.15@90.392,108.65 94.298,108.65 94.907,108.04 97.977,108.04 98.587,108.65 UM4.15@105.4,108.65
  Bottom Layer w0.203: P6.46@91.3,75.6 91.216,75.684 91.216,80.4 v1(91.781,80.965) 91.216,81.53 91.216,108.112 v1(91.756,108.651)
MA6: P6.43 RM7.2 UM1.16 UM2.16 UM3.16 UM4.16 UM5.16 UM6.16 UM7.16 UM8.16 | length 156.8
  Top Layer w0.203: UM5.16@60.375,82.229 64.424,82.229 65.033,81.62 73.314,81.62 73.923,82.229 UM6.16@75.383,82.229 79.353,82.229 79.986,81.596 88.505,81.596 89.138,82.229 UM7.16@90.392,82.229 94.526,82.229 95.136,81.62 97.977,81.62 98.587,82.229 UM8.16@105.4,82.229 107.129,82.229 107.656,81.702 126.3,81.702 127.252,80.75 RM7.2@132.1,80.75 ; UM1.16@60.375,109.92 64.424,109.92 65.033,109.31 73.314,109.31 73.923,109.92 UM2.16@75.383,109.92 78.082,109.92 78.715,109.286 v1(87.59,109.286) 88.429,109.286 88.984,109.842 90.314,109.842 UM3.16@90.392,109.92 94.526,109.92 95.136,109.31 97.977,109.31 98.587,109.92 UM4.16@105.4,109.92
  Bottom Layer w0.203: v1(87.59,109.286) 87.59,76.774 88.225,76.139 88.225,74.925 89.3,73.85 P6.43@89.3,73.6
  other v1: 87.59,81.596
MA7: P6.44 RM8.2 UM1.17 UM2.17 UM3.17 UM4.17 UM5.17 UM6.17 UM7.17 UM8.17 | length 148
  Top Layer w0.203: UM5.17@60.375,83.499 64.424,83.499 65.033,82.89 73.314,82.89 73.923,83.499 UM6.17@75.383,83.499 79.353,83.499 79.986,82.866 88.505,82.866 89.138,83.499 UM7.17@90.392,83.499 94.603,83.499 95.212,82.89 97.977,82.89 98.587,83.499 UM8.17@105.4,83.499 105.411,83.488 106.556,83.488 107.419,82.625 RM8.2@123.1,82.625 ; UM1.17@60.375,111.19 64.424,111.19 65.033,110.58 73.314,110.58 73.923,111.19 UM2.17@75.383,111.19 78.082,111.19 78.715,110.556 88.168,110.556 88.499,110.887 88.663,110.887 88.966,111.19 UM3.17@90.392,111.19 94.447,111.19 95.057,110.58 97.977,110.58 98.587,111.19 UM4.17@105.4,111.19
  Bottom Layer w0.203: v1(88.606,110.887) 88.606,110.861 89.572,109.896 89.572,91.43 88.113,89.971 88.113,86.28 88.149,86.244 88.149,77.001 89.3,75.85 P6.44@89.3,75.6
  other v1: 88.149,82.87
MA8: P6.41 RM9.2 UM1.18 UM2.18 UM3.18 UM4.18 UM5.18 UM6.18 UM7.18 UM8.18 | length 159.5
  Top Layer w0.203: UM5.18@60.375,84.769 64.424,84.769 65.033,84.16 73.314,84.16 73.923,84.769 UM6.18@75.383,84.769 79.353,84.769 79.986,84.136 v1(86.473,84.136) 88.378,84.136 89.011,84.769 UM7.18@90.392,84.769 94.686,84.769 95.296,84.16 103.637,84.16 104.24,84.762 105.393,84.762 UM8.18@105.4,84.769 106.221,84.769 106.372,84.619 106.416,84.619 107.885,83.15 117.008,83.15 117.232,83.374 126.15,83.374 126.9,82.625 RM9.2@132.1,82.625 ; UM1.18@60.375,112.46 64.424,112.46 65.033,111.85 73.314,111.85 73.923,112.46 UM2.18@75.383,112.46 78.082,112.46 78.715,111.826 v1(86.473,111.826) 87.921,111.826 88.554,112.46 UM3.18@90.392,112.46 94.603,112.46 95.212,111.85 97.977,111.85 98.587,112.46 UM4.18@105.4,112.46
  Bottom Layer w0.203: v1(86.473,111.826) 86.473,79.336 86.486,79.323 86.486,74.664 87.3,73.85 P6.41@87.3,73.6
MA9: P6.42 RM10.2 UM1.19 UM2.19 UM3.19 UM4.19 UM5.19 UM6.19 UM7.19 UM8.19 | length 152.8
  Top Layer w0.203: UM5.19@60.375,87.309 64.424,87.309 65.033,86.7 73.314,86.7 73.923,87.309 UM6.19@75.383,87.309 79.185,87.309 79.92,86.574 v1(87.032,86.574) 88.946,86.574 89.681,87.309 94.603,87.309 95.212,86.7 97.768,86.7 98.377,87.309 UM8.19@105.4,87.309 105.422,87.287 108.136,87.287 v1(108.139,87.29) ; UM1.19@60.375,115 64.58,115 65.189,114.39 68.081,114.39 68.691,115 UM2.19@75.383,115 78.701,115 79.436,114.265 86.93,114.265 v1(86.981,114.316) ; v1@86.981,114.265 87.716,115 UM3.19@90.392,115 94.603,115 95.212,114.39 97.977,114.39 98.587,115 UM4.19@105.4,115 ; v1(108.179,84.353) 122.953,84.353 RM10.2@123.1,84.5
  Bottom Layer w0.203: v1(86.981,114.316) 87.032,114.265 v1(87.032,86.574) 87.032,76.334 87.3,76.066 P6.42@87.3,75.6 ; v1(108.139,87.29) 108.159,87.27 108.159,84.373 v1(108.179,84.353)
MA10: P6.39 RM11.2 UM1.7 UM2.7 UM3.7 UM4.7 UM5.7 UM6.7 UM7.7 UM8.7 | length 169.1
  Top Layer w0.203: UM5.7@51.739,84.769 58.673,84.769 59.282,85.379 64.605,85.379 65.215,84.769 UM6.7@66.747,84.769 73.085,84.769 73.695,85.379 79.439,85.379 80.048,84.769 UM7.7@81.756,84.769 88.325,84.769 88.935,85.379 94.806,85.379 95.415,84.769 UM8.7@96.764,84.769 UM8.7@97.475,84.769 ; UM1.7@51.739,112.46 58.673,112.46 59.36,113.147 62.368,113.147 62.495,113.02 64.502,113.02 65.062,112.46 UM2.7@66.747,112.46 73.085,112.46 73.695,113.069 78.167,113.069 78.777,112.46 UM3.7@81.756,112.46 v1(84.288,112.46) 87.868,112.46 88.478,113.069 94.806,113.069 95.415,112.46 UM4.7@96.764,112.46 ; UM8.7@96.824,84.709 103.403,84.709 104.115,85.42 112.289,85.42 112.33,85.461 125.587,85.461 126.549,84.5 RM11.2@132.1,84.5
  Bottom Layer w0.203: v1(84.288,112.46) 84.307,112.441 84.307,84.788 v1(84.288,84.769) 84.288,75.147 85.077,74.359 85.077,74.289 85.3,74.066 P6.39@85.3,73.6
MA11: P6.40 RM12.2 UM1.6 UM2.6 UM3.6 UM4.6 UM5.6 UM6.6 UM7.6 UM8.6 | length 162.6
  Top Layer w0.203: UM5.6@51.739,87.309 58.673,87.309 59.282,87.919 64.605,87.919 65.215,87.309 UM6.6@66.747,87.309 73.085,87.309 73.695,87.919 79.439,87.919 80.048,87.309 UM7.6@81.756,87.309 v1(85.3,87.309) 88.803,87.309 89.413,87.919 94.806,87.919 95.415,87.309 97.475,87.309 98.116,87.95 v1(98.843,87.95) ; UM1.6@51.739,115 58.673,115 59.282,115.609 64.605,115.609 65.215,115 UM2.6@66.747,115 66.778,115.03 67.884,115.03 68.462,115.609 78.828,115.609 79.377,115.06 81.696,115.06 UM3.6@81.756,115 v1(85.3,115) 86.903,115 87.512,115.609 94.806,115.609 95.415,115 UM4.6@96.764,115 ; v1(98.817,85.309) 103.337,85.309 103.88,85.852 111.806,85.852 112.329,86.375 RM12.2@123.1,86.375
  Bottom Layer w0.203: P6.40@85.3,75.6 v1(85.3,87.309) 84.847,87.762 84.847,114.547 v1(85.3,115) ; v1(98.817,85.309) 98.83,85.322 98.83,87.938 v1(98.843,87.95)
MASTER#: P7.47 P8.72 P9.72 R40.1 U1.198 | length 170.8
  Top Layer w0.203: v1(155.866,91.964) 170.143,91.964 171.058,92.878 172.426,92.878 176.903,97.354 178.444,97.354 U1.198@178.463,97.336
  Layer 2 w0.203: P7.47@93.3,129.2 93.3,129.166 93.668,128.798 93.702,128.798 94.519,127.981 102.953,127.981 108.465,122.469 113.798,122.469 115.474,124.145 123.227,124.145 124.577,122.795 128.821,122.795 131.71,119.906 v1(131.71,119.855)
  Bottom Layer w0.203: R40.1@92.275,125.7 92.275,127.281 93.148,128.153 93.148,129.048 P7.47@93.3,129.2 ; v1(131.71,119.855) 131.71,118.938 134.811,115.838 134.811,115.519 142.714,107.616 150.373,107.616 152.411,105.578 152.411,103.902 155.866,100.447 v1(155.866,91.964) 155.815,91.913 155.815,85.954 155.866,85.903 142.342,72.379 142.342,61.269 139.483,58.41 139.483,50.233 138.5,49.25 P8.72@138.5,49 138.5,47.638 139.437,46.701 139.437,45.187 138.5,44.25 P9.72@138.5,44
MCU_ADC07: C99.1 R152.1 RT1.1 U2.13 | length 147.7
  Top Layer w0.305: C99.1@107.124,21.704 109.664,21.704 v2(109.703,21.742) ; v2(110.211,11.125) 111.582,11.125 ; RT1.1@190.817,90.983 190.817,91.884 v2(190.805,91.897) 190.817,91.91 190.817,93.688 R152.1@190.83,93.701
  Layer 2 w0.305: v2(110.211,11.125) 109.703,11.633 v2(109.703,21.742) 109.703,37.77 128.27,56.337 172.669,56.337 182.372,66.04 182.372,79.172 189.205,86.004 189.205,91.072 190.03,91.897 v2(190.805,91.897)
MCU_ADC10: C90.1 R99.1 U2.9 | length 5.4
  Top Layer w0.203: R99.1@105.321,14.076 C90.1@107.121,14.076 107.71,13.487 108.886,13.487 109.001,13.603 U2.9@110.431,13.603
MCU_ADC11: R95.2 U2.10 | length 227.9
  Top Layer w0.203: U2.10@110.431,13.103 110.446,13.117 112.838,13.117 v1(112.852,13.132) ; v1(209.891,115.179) 209.841,115.23 209.841,121.275 210.984,122.418 212.101,122.418 212.914,123.231 215.454,123.231 216.572,124.349 R95.2@216.572,125.265
  Bottom Layer w0.203: v1(112.852,13.132) 113.487,12.497 115.367,12.497 115.9,13.03 125.515,13.03 139.663,27.178 177.648,27.178 190.043,39.573 207.303,39.573 208.293,40.564 219.253,40.564 220.559,41.87 220.559,53.559 215.048,59.071 205.853,59.071 201.205,63.719 201.205,106.492 v1(209.891,115.179)
MCU_ADC12: C91.1 R90.1 U2.11 | length 5.3
  Top Layer w0.203: R90.1@105.321,12.176 C91.1@107.121,12.176 107.548,12.603 U2.11@110.431,12.603
MEMCS16#: P7.17 P8.50 P9.50 R33.1 U1.4 | length 216.8
  Top Layer w0.203: P7.17@63.3,129.2 63.3,129.45 64.4,130.55 64.4,137.226 66.136,138.962 106.381,138.962 117.289,128.054 121.35,128.054 122.769,126.635 122.769,125.947 v1(122.72,125.897) ; v1@169.493,98.839 170.171,98.839 174.305,102.973 U1.4@174.305,104.994
  Bottom Layer w0.203: P7.17@63.3,129.2 63.3,126.415 63.532,126.183 63.571,126.183 63.913,125.84 R33.1@63.913,125.802 ; v1(122.72,125.897) 124.212,124.405 127.912,124.405 130.913,121.403 135.064,121.403 139.738,126.077 159.471,126.077 169.591,115.957 169.591,103.996 169.493,103.898 v1(169.493,98.796) 169.493,80.877 169.007,80.391 169.007,77.434 167.979,76.406 167.979,71.993 165.134,69.148 165.134,55.334 161.485,51.685 161.485,50.235 160.5,49.25 P8.50@160.5,49 160.5,47.638 161.437,46.701 161.437,45.187 P9.50@160.5,44.25
MEMR#: P7.34 P8.63 P9.63 R36.1 U1.171 U3.24 | length 236
  Top Layer w0.203: U3.24@107.402,50.612 107.481,50.612 108.357,51.489 113.738,51.489 115.377,49.85 122.769,49.85 129.729,42.891 144.791,42.891 145.579,43.678 145.579,44.829 146.5,45.75 P9.63@146.5,46 ; v1@158.971,83.759 159.825,83.759 159.839,83.745 160.302,83.745 160.316,83.759 168.281,83.759 168.357,83.836 U1.171@178.463,83.836
  Layer 2 w0.203: P7.34@79.3,131.2 79.3,130.95 80.275,129.975 80.275,127.346 81.113,126.508 83.628,126.508 85.33,124.806 86.803,124.806 88.708,122.901 98.044,122.901 98.922,122.023 100.573,122.023 102.181,120.415 102.181,118.779 103.509,117.451 114.935,117.451 117.613,114.773 121.779,114.773 124.37,112.182 128.184,112.182 129.553,113.551 129.553,114.292 129.907,114.646 132.56,114.646 135.489,117.574 137.951,117.574 v1(138.009,117.516)
  Bottom Layer w0.203: R36.1@79.142,125.7 79.142,127.133 78.269,128.006 78.269,129.919 79.3,130.95 P7.34@79.3,131.2 ; v1(138.009,117.516) 138.009,117.468 144.497,110.98 156.407,110.98 159.865,107.522 159.865,84.888 v1(158.812,83.836) 152.056,77.079 152.056,72.71 149.135,69.789 149.135,66.691 146.5,64.056 P8.63@146.5,51 ; P9.63@146.384,46.116 146.384,46.865 145.695,47.554 145.695,49.583 146.067,49.955 146.067,50.101 146.5,50.534 P8.63@146.5,50.564
MEMW#: P7.36 P8.64 P9.64 R35.1 U1.172 | length 189.4
  Top Layer w0.203: v1(160.071,84.304) 160.102,84.336 U1.172@178.463,84.336
  Layer 2 w0.203: P7.36@81.3,131.2 81.3,130.95 82.307,129.943 82.307,128.286 82.993,127.6 83.958,127.6 85.736,125.822 87.157,125.822 89.191,123.788 100.42,123.788 103.44,120.767 103.44,119.825 104.987,118.278 115.861,118.278 116.46,117.678 116.868,117.678 118.08,116.467 122.142,116.467 124.195,114.414 128.05,114.414 129.323,115.687 132.142,115.687 135.165,118.71 137.755,118.71 v1(137.781,118.735)
  Bottom Layer w0.203: R35.1@80.783,125.7 80.783,127.117 80.326,127.574 80.326,129.976 81.3,130.95 P7.36@81.3,131.2 ; v1(137.781,118.735) 137.781,118.707 138.805,117.683 138.805,117.307 144.62,111.492 156.619,111.492 160.438,107.674 160.438,84.671 v1(160.071,84.304) 152.567,76.801 152.567,72.511 149.668,69.612 149.668,66.487 147.077,63.897 147.077,52.594 147.509,52.162 147.509,50.259 146.5,49.25 P8.64@146.5,49 146.5,47.638 147.437,46.701 147.437,45.187 146.5,44.25 P9.64@146.5,44
MOUSE_KEYL: P4.18 U2.31 | length 133
  Top Layer w0.203: v1(116.542,15.298) 116.61,15.298 116.806,15.103 U2.31@118.581,15.103 ; P4.18@125.3,129.6 125.55,129.6 126.458,128.692 127.9,128.692 129.5,127.092 129.5,114.222 129.061,113.782 v1(128.994,113.782)
  Bottom Layer w0.203: v1(116.542,15.298) 116.535,15.305 116.535,18.974 118.593,21.031 118.593,24.943 119.504,25.855 119.504,44.376 127.327,52.199 127.327,57.841 131.212,61.726 131.212,70.626 128.84,72.998 128.84,77.065 136.827,85.052 136.827,99.54 128.994,107.372 v1(128.994,113.782)
MOUSE_KEYR: P4.17 U2.32 | length 130.4
  Top Layer w0.203: v1(117.094,16.053) 117.544,15.603 U2.32@118.581,15.603 ; P4.17@127.3,129.6 127.766,129.6 130.059,127.306 130.059,113.481 v1(130.112,113.428)
  Bottom Layer w0.203: v1(117.094,16.053) 117.094,18.618 119.075,20.599 119.075,24.663 119.969,25.557 119.969,44.184 127.787,52.003 127.787,57.65 131.672,61.535 131.672,70.817 129.3,73.189 129.3,76.875 137.291,84.865 137.291,99.794 129.831,107.254 129.831,113.065 130.112,113.346 v1(130.112,113.428) ; P4.17@127.05,129.6 P4.17@127.3,129.6
MSCLK: C8.1 P2.5 R43.1 U1.34 | length 67.1
  Top Layer w0.254: U1.34@159.305,104.994 159.305,102.825 160.209,101.92 162.114,101.92 163.74,103.546 v1(166.635,103.546) ; v1(167.677,112.157) 181.139,112.157 195.896,126.914 R43.1@199.757,126.914 199.757,128.692 202.8,131.735 P2.5@202.8,135
  Bottom Layer w0.254: v1(166.635,103.546) 166.635,107.483 167.677,108.524 v1(167.677,112.157)
MTR0#: P7.6 U12.2 | length 51.2
  Top Layer w0.203: v1(37.606,87.109) 37.689,87.109 37.78,87.2 38.997,87.2 U12.2@39.026,87.229
  Bottom Layer w0.203: v1(37.606,87.109) 38.01,87.513 38.01,88.712 39.587,90.29 39.587,109.644 49.948,120.005 49.948,127.117 50.495,127.665 50.495,130.145 51.3,130.95 P7.6@51.3,131.2
MTR1#: P7.5 U12.5 | length 46.2
  Top Layer w0.203: U12.5@39.026,89.179 39.034,89.187 40.414,89.187 v1(40.423,89.195)
  Bottom Layer w0.203: v1(40.423,89.195) 40.364,89.253 40.364,89.742 40.104,90.003 40.104,109.425 50.43,119.751 50.43,126.812 51.3,127.682 P7.5@51.3,129.2
NA2: P6.11 U1.45 | length 131.2
  Top Layer w0.203: v1@61.124,102.276 65.947,102.276 68.078,104.408 107.083,104.408 113.429,110.754 139.438,110.754 141.373,108.819 152.752,108.819 153.805,107.766 U1.45@153.805,104.994
  Bottom Layer w0.203: P6.11@57.3,73.6 57.3,74.066 57.044,74.321 57.044,74.326 56.399,74.971 56.399,76.19 59.168,78.959 59.168,99.609 61.124,101.565 v1(61.124,102.301)
NA23: P6.14 U1.44 | length 128.3
  Top Layer w0.203: v1@62.317,102.86 65.894,102.86 67.823,104.789 106.827,104.789 113.247,111.208 139.69,111.208 141.58,109.319 152.959,109.319 154.305,107.973 U1.44@154.305,104.994
  Bottom Layer w0.203: P6.14@59.3,75.6 59.3,76.602 60.666,77.968 60.666,98.593 61.759,99.685 61.759,102.327 v1(62.317,102.886)
NADS#: P6.12 U1.54 | length 119.1
  Top Layer w0.203: v1@60.259,99.711 66.671,99.711 69.232,102.271 108.086,102.271 114.248,108.433 138.152,108.433 144.749,101.836 U1.54@147.647,101.836
  Bottom Layer w0.203: P6.12@57.3,75.6 57.3,75.973 59.65,78.324 59.65,99.155 v1(60.259,99.763)
NBUSY#: P6.7 U1.47 | length 132.7
  Top Layer w0.203: v1@58.228,100.854 58.939,100.854 59.828,101.743 62.055,101.743 62.108,101.796 66.103,101.796 68.299,103.992 107.304,103.992 113.611,110.3 139.215,110.3 141.175,108.34 151.233,108.34 152.805,106.768 U1.47@152.805,104.994
  Bottom Layer w0.203: P6.7@53.3,73.6 53.3,73.85 52.495,74.655 52.495,76.183 52.505,76.194 52.505,76.408 53.075,76.978 54.24,76.978 57.745,80.483 57.745,96.764 57.314,97.196 57.314,99.914 v1(58.228,100.828)
NDC#: U1.49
